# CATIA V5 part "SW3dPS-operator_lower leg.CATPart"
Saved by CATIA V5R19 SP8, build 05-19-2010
Part number: SW3dPS-operator_lower leg
Revision: ANY
Definition: SW3dPS-operator_lower leg
Source: Unknown
Bounding box of the stored display mesh (mm): x -54.61 to 54.61, y -415.29 to 54.61, z -54.61 to 54.61
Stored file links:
  G:\EU_thinkMotion\CFAO_2010\MMS_groupe1\MMS_groupe1\OK\rragonneau\rragonneau\SW3dPS-operator_lower leg.CATPart
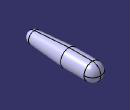
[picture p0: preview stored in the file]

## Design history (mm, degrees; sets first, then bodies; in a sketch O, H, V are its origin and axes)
Body1 "NONE" (main body)
  Solid1 "Manifold Solid #10999": solid without history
